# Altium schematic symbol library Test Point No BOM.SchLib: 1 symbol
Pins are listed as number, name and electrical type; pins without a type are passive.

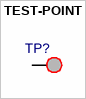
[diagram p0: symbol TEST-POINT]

## TEST-POINT
designator TP?, comment SMD Test Point  (value not drawn)  (no BOM)
Test Point pad 1.00mm
footprint TP_1x1_SMD
pins: 1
